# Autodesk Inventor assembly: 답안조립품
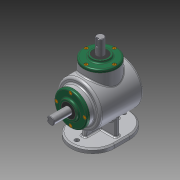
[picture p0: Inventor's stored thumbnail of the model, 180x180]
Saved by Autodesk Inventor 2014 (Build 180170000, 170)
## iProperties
Created: 2016-04
Part Number: 답안조립품
Document SubType Name: Assembly
Designer: basic
Author: basic
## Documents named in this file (14)
- C:\Users\basic\Desktop\460408V1011\답안조립품.iam
- C:\Users\basic\Desktop\460408V1011\본채.ipt
- C:\Users\basic\Desktop\460408V1011\커버.ipt
- C:\Users\basic\Desktop\460408V1011\베어링 6203.ipt
- C:\Users\basic\Desktop\460408V1011\오일실 17 32 8.ipt
- C:\Users\basic\Desktop\460408V1011\M4.ipt
- C:\Users\basic\Desktop\460408V1011\메인 축.ipt
- 메인 축.ipt
- C:\Users\basic\Desktop\460408V1011\메인 베벨기어.ipt
- C:\Users\basic\Desktop\460408V1011\키 5x5.ipt
- C:\Users\basic\Desktop\460408V1011\키 4x4.ipt
- C:\Users\basic\Desktop\460408V1011\서브 베벨기어.ipt
- C:\Users\basic\Desktop\460408V1011\서브 축.ipt
- 서브 축.ipt
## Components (8 placed, 1 different names)
1. M4:2
2. M4:3
3. M4:4
4. M4:5
5. M4:1
6. M4:6
7. M4:7
8. M4:8
